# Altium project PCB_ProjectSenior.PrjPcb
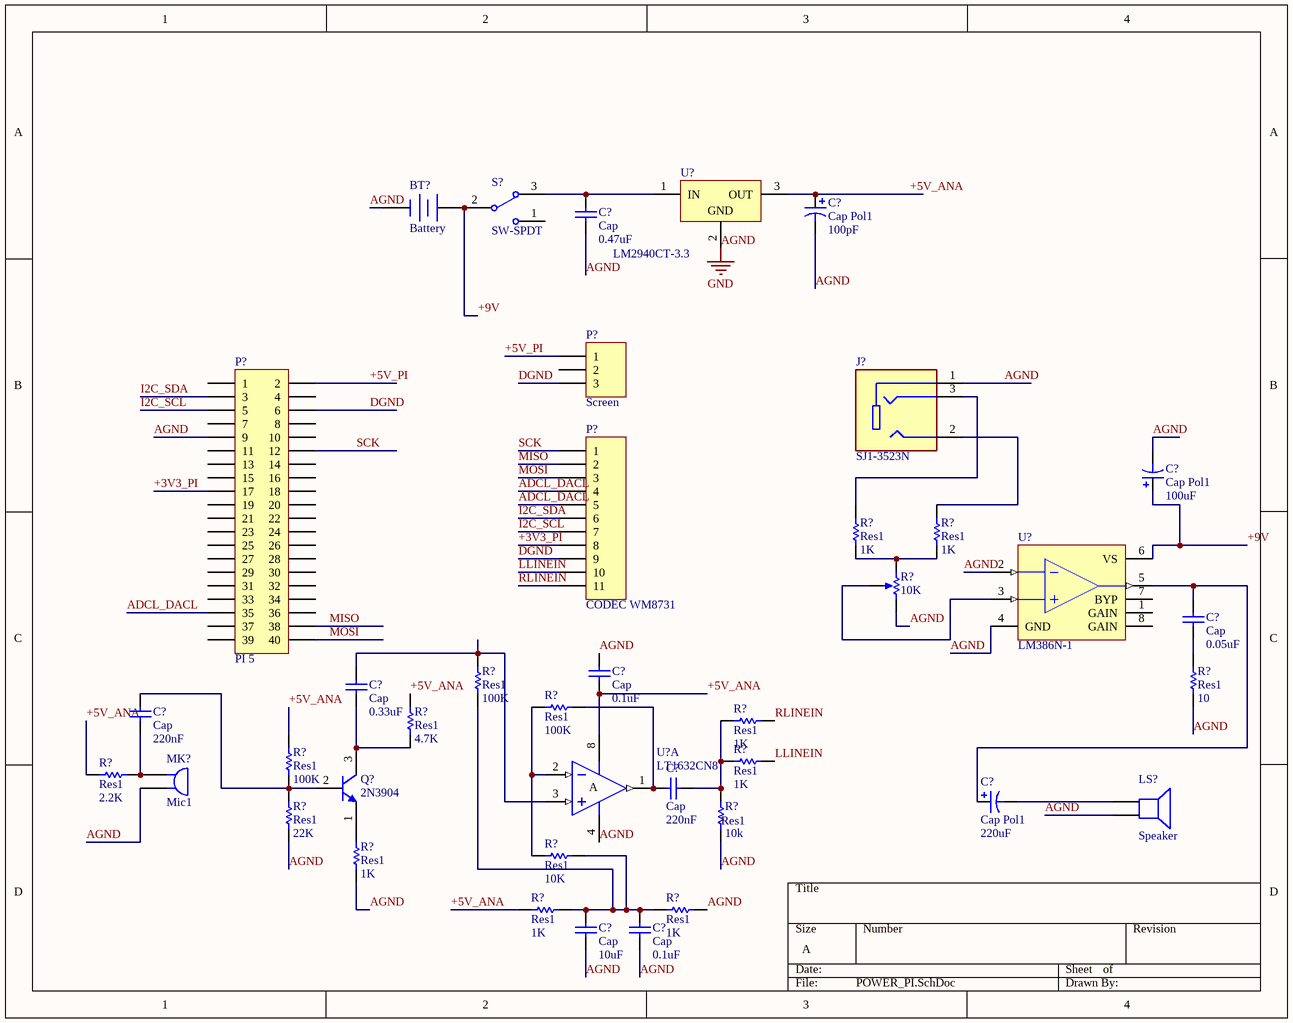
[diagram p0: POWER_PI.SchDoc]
2 sheets, 40 parts. Net scope: global (net labels, ports and power ports of the same name join across sheets).
Sheets:
  POWER_PI.SchDoc
  CODEC_INTERFACE.SchDoc

## Sheet POWER_PI.SchDoc
size A; SheetNumber: 1; SheetTotal: 2

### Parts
(Parts that share a designator on the sheet are numbered #1, #2 ... from top to bottom, then left to right.)
BT?  Battery  [BAT-2]
C?#1  Cap Pol1  value 100pF  [RB7.6-15]
C?#2  Cap  value 0.47uF  [RAD-0.3]
C?#3  Cap Pol1  value 100uF  [RB7.6-15]
C?#4  Cap  value 0.05uF  [RAD-0.3]
C?#5  Cap  value 0.1uF  [RAD-0.3]
C?#6  Cap  value 0.33uF  [RAD-0.3]
C?#7  Cap  value 220nF  [RAD-0.3]
C?#8  Cap  value 220nF  [RAD-0.3]
C?#9  Cap Pol1  value 220uF  [RB7.6-15]
C?#10  Cap  value 10uF  [RAD-0.3]
C?#11  Cap  value 0.1uF  [RAD-0.3]
J?  SJ1-3523N  [CUI_SJ1-3523N]
LS?  Speaker  [PIN2]
MK?  Mic1  [PIN2]
P?#1  Screen  [HDR1X3]
P?#2  PI 5  [HDR2X20]
P?#3  CODEC WM8731  [HDR1X11]
Q?  2N3904  [TO92C]
R?#1  Res1  value 1K  [AXIAL-0.3]
R?#2  Res1  value 1K  [AXIAL-0.3]
R?#3  value 10K  [POT OFFSET 200]  (hidden comment: RPot_3)
R?#4  Res1  value 100K  [AXIAL-0.3]
R?#5  Res1  value 100K  [AXIAL-0.3]
R?#6  Res1  value 10  [AXIAL-0.3]
R?#7  Res1  value 1K  [AXIAL-0.3]
R?#8  Res1  value 4.7K  [AXIAL-0.3]
R?#9  Res1  value 1K  [AXIAL-0.3]
R?#10  Res1  value 2.2K  [AXIAL-0.3]
R?#11  Res1  value 100K  [AXIAL-0.3]
R?#12  Res1  value 22K  [AXIAL-0.3]
R?#13  Res1  value 10k  [AXIAL-0.3]
R?#14  Res1  value 10K  [AXIAL-0.3]
R?#15  Res1  value 1K  [AXIAL-0.3]
R?#16  Res1  value 1K  [AXIAL-0.3]
R?#17  Res1  value 1K  [AXIAL-0.3]
S?  SW-SPDT  [SW DPST jameco]
U?#1  LM2940CT-3.3  [T03B]
U?#2  LM386N-1  [DIP-8]
U?#3  LT1632CN8  [DIP-8]  (part A of 2)

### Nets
AGND: BT?.2(-) C?#1.2 C?#2.1 C?#3.2 C?#5.2 C?#10.1 C?#11.1 J?.1 LS?.2 MK?.2 P?#2.9 R?#3.3(BOT) R?#6.1 R?#12.1 R?#13.1 R?#15.1 R?#17.2 U?#1.2(GND) U?#2.2(IN-) U?#2.4(GND) U?#3.4(V-)  [also labelled GND]
+3V3_PI: P?#2.17 P?#3.8
+5V_ANA: C?#1.1 C?#5.1 R?#8.2 R?#10.1 R?#11.2 R?#16.1 U?#1.3(OUT) U?#3.8(V+)
+5V_PI: P?#1.1 P?#2.2
+9V: BT?.1(+) C?#3.1 S?.2 U?#2.6(VS)
ADCL_DACL: P?#2.35 P?#3.4 P?#3.5
DGND: P?#1.3 P?#2.6 P?#3.9
I2C_SCL: P?#2.5 P?#3.7
I2C_SDA: P?#2.3 P?#3.6
LLINEIN: P?#3.10 R?#9.2
MISO: P?#2.38 P?#3.2
MOSI: P?#2.40 P?#3.3
RLINEIN: P?#3.11 R?#7.2
SCK: P?#2.12 P?#3.1
NetC?#2_2: C?#2.2 S?.3 U?#1.1(IN)
NetC?#4_1: C?#4.1 R?#6.2
NetC?#4_2: C?#4.2 C?#9.1 U?#2.5(OUT)
NetC?#6_1: C?#6.1 Q?.3(C) R?#8.1
NetC?#6_2: C?#6.2 R?#4.2 U?#3.3(IN+)
NetC?#7_1: C?#7.1 MK?.1 R?#10.2
NetC?#7_2: C?#7.2 Q?.2(B) R?#11.1 R?#12.2
NetC?#8_1: C?#8.1 R?#5.2 U?#3.1(OUT)
NetC?#8_2: C?#8.2 R?#7.1 R?#9.1 R?#13.2
NetC?#9_2: C?#9.2 LS?.1
NetC?#10_2: C?#10.2 C?#11.2 R?#4.1 R?#14.2 R?#16.2 R?#17.1
NetJ?_2: J?.2 R?#2.2
NetJ?_3: J?.3 R?#1.2
NetQ?_1: Q?.1(E) R?#15.2
NetR?#1_1: R?#1.1 R?#2.1 R?#3.1(TOP)
NetR?#3_2: R?#3.2(TAP) U?#2.3(IN+)
NetR?#5_1: R?#5.1 R?#14.1 U?#3.2(IN-)

Not connected (* = marked no-connect by the designer): P?#1 2; P?#2 1 4 7 8 10 11 13 14 15 16 18 19 20 21 22 23 24 25 26 27 28 29 30 31 32 33 34 36 37 39; S? 1; U?#2 1(GAIN) 7(BYP) 8(GAIN)

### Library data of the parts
BT? = Battery: Multicell Battery
C?#1 C?#3 C?#9 = Cap Pol1: Polarized Capacitor (Radial)
C?#2 C?#4-C?#8 C?#10 C?#11 = Cap: Capacitor
J? = SJ1-3523N: 3.5 mm, Stereo, Right Angle, Through Hole, 3 Conductors, 0 Internal Switches, Audio Jack Connector; MF: Same Sky
LS? = Speaker: Loudspeaker
MK? = Mic1: Microphone
P?#1 = Header 3: Header, 3-Pin
P?#2 = Header 20X2: Header, 20-Pin, Dual row
P?#3 = Header 11: Header, 11-Pin
Q? = 2N3904: NPN General Purpose Amplifier
R?#1 R?#2 R?#4-R?#17 = Res1: Resistor
R?#3 = RPot: Potentiometer; Sim Note: Enter the Resistance value and the set point into parameter fields.; Set Position: 0.5
S? = SW-SPDT: SPDT Subminiature Toggle Switch, Right Angle Mounting, Vertical Actuation
U?#1 = LM2940CT-5.0: 1A Low Dropout Regulator, 3-pin TO-220; Manufacturer: National Semiconductor; PackageTopMarking: NSUZXYTTE#*LM2940CT*-5.0 P+; PowerWise: N; CompType: LDO IC; High-Reliability: Y
U?#2 = LM386N-1: Low-Voltage Audio Power Amplifier
U?#3 = LT1632CN8: 45MHz, 45V/µs, Dual Rail-to-Rail Input and Output Precision Operational Amplifier; Note: 1455

## Sheet CODEC_INTERFACE.SchDoc
size A; SheetNumber: 2; SheetTotal: 2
